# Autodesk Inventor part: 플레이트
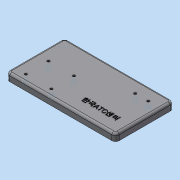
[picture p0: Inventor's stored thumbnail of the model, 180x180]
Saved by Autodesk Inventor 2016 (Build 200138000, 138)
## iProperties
Created: 2018-01
Part Number: 플레이트
Material: 알루미늄 6061
Document SubType Name: Modeling
Designer: mduedu
Density: 2.71 g/cm^3
Appearance: 기본값
Mass: 319.562 g
Surface Area: 287.617 cm^2
Volume: 117.92 cm^3
Author: mduedu
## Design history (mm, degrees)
sketch "스케치1"
  geometry: L1 (75, 40)-(-75, 40); L2 (-75, 40)-(-75, -40); L3 (-75, -40)-(75, -40); L4 (75, -40)-(75, 40); L5 (75, 40)-(-75, -40); L6 (-75, 40)-(75, -40); 1 further point
  constraints: 12 end point, 2 midpoint, 2 parallel, 1 horizontal, 1 perpendicular
  dimensions: "d0" = 150 distance of L3.end L2.end; "d1" = 80 distance of L2.end L1.end
extrude "돌출1" new body sketch "스케치1" distance "d2" = 10; taper "d3" = 0 deg
fillet "모깎기1" dims "d4" = 5
fillet "모깎기2" dims "d5" = 3
sketch "스케치2"
  geometry: L1 (-70, 40)-(70, 40) reference; L2 (-75, -35)-(-75, 35) reference; 5 further points
  constraints: 2 horizontal alignment, 2 vertical alignment
  dimensions: "d6" = 10 distance from line of point (-58, 30) L1; "d7" = 35 distance of point (-23, 30) point (-58, 30); "d8" = 31 distance of point (-58, -1) point (-58, 30); "d9" = 17 distance from line of point (-58, 30) L2
sketch "스케치3"
  geometry: 4 further points
  constraints: 4 other
hole "구멍1" sketch "스케치3" at (-23, 30), (-58, -1), (-23, -1), (-58, 30) diameter "d10" = 3.4; stored, may be unused: countersink angle "d14" = 90 deg, drill point angle "d16" = 0 deg; dims "d11" = 6, "d12" = 6.5, "d13" = 3.4, "d15" = 8
sketch "스케치4"
  geometry: L1 (75, 35)-(75, -35) reference; L2 (70, -40)-(-70, -40) reference; 3 further points
  constraints: 1 horizontal alignment
  dimensions: "d17" = 17 distance from line of point (58, -22) L1; "d18" = 18 distance of point (40, -22) point (58, -22); "d19" = 18 distance from line of point (58, -22) L2
sketch "스케치5"
  geometry: 2 further points
  constraints: 2 other
hole "구멍2" sketch "스케치5" at (40, -22), (58, -22) diameter "d20" = 3.4; stored, may be unused: countersink angle "d24" = 90 deg, drill point angle "d26" = 0 deg; dims "d21" = 6, "d22" = 6.5, "d23" = 3.4, "d25" = 8
sketch "스케치6"
  geometry: L1 (75, -35)-(75, 35) reference; L2 (-70, -40)-(70, -40) reference; 2 further points
  constraints: 1 other
  dimensions: "d27" = 40 distance from line of point (35, -20) L1; "d28" = 20 distance from line of point (35, -20) L2
feature "엠보싱1" sketch "스케치6" dims "d0" = 150, "d29" = 0.5, "d30" = 0
node "솔리드1"
